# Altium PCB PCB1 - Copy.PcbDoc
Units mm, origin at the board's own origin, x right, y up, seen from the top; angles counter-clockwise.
Board outline 16 x 12 mm, 2 copper layers (Top Layer, Bottom Layer); 5 components, 7 nets, 19 pads, 7 vias.
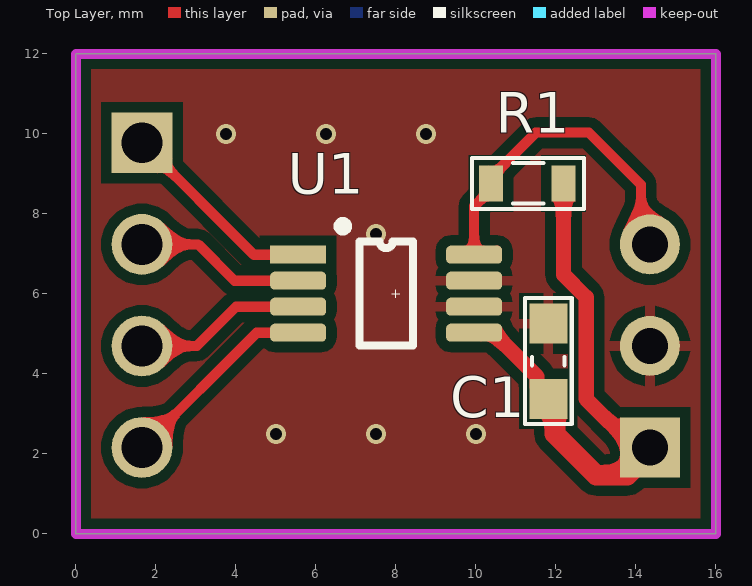
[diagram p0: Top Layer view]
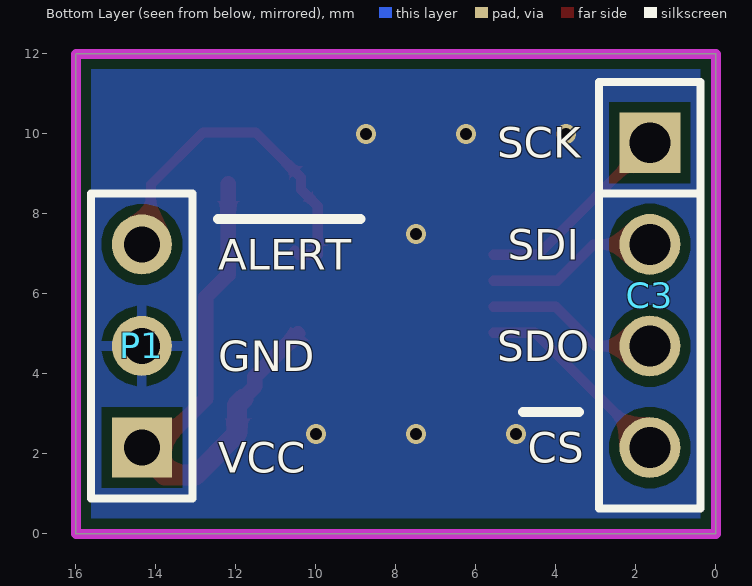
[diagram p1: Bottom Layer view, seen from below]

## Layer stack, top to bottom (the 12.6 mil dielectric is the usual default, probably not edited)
Top Solder: solder mask 0.0102, Solder Resist, Dk 3.5
Top Layer: signal copper 0.0356
Dielectric 1: dielectric 0.32, FR-4, Dk 4.8
Bottom Layer: signal copper 0.0356
Bottom Solder: solder mask 0.0102, Solder Resist, Dk 3.5

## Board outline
0,0 0,12 16,12 16,0

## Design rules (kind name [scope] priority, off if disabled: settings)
Clearance [All] p1: gap=0.254 ignorepadtopadclearanceinfootprint=TRUE
PolygonConnect [All] p1: connectstyle=Relief reliefconductorwidth=0.254 reliefentries=4 polygonreliefangle="90 Angle" airgapwidth=0.254
RoutingVias [All] p1: holewidth=0.711 width=1.27 viastyle="Through Hole" minholewidth=0.2 minwidth=0.3 maxholewidth=0.711 maxwidth=1.27
SolderMaskExpansion [All] p1: expansion=0.102 istentingtop=FALSE
Width [All] p1: maxlimit=1.27 minlimit=0.254 preferedwidth=0.254 minimp=50.000000 maximp=50.000000 favimp=50.000000
30 further rules are at their usual default settings.

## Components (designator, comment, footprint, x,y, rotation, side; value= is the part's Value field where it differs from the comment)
C1 "100nF" CAP_0603 11.811,4.318 r270 top value=33p
C3 "JP4" JP4-C1T 1.651,9.779 r270 bottom
P1 "Header 3" HDR1X3 14.351,2.159 r90 bottom
R1 "10k" RES-SMD-0603 11.303,8.763 r180 top
U1 "TMAG5170" SOP8 8,6 r0 top

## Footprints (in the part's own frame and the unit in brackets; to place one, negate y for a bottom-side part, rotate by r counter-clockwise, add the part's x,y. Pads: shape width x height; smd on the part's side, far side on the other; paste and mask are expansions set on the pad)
CAP_0603 [mm]
  rect 1x0.95 smd mask+0.076: 1(-0.94,0) 2(0.94,0)
  silkscreen extent -1.57,-0.58 1.57,0.58, body extent -0.77,-0.39 0.83,0.41, height 0.9
HDR1X3 [mm] "Connector; Header; 3 Position"
  rect 1.5x1.5 hole 0.9: 1(0,0)
  round 1.5 hole 0.9: 2(2.54,0) 3(5.08,0)
  silkscreen extent -1.27,-1.27 6.35,1.27, body extent -1.27,-1.27 6.35,1.27, height 7
JP4-C1T [mm] "4 row, straight, gold plating"
  rect 1.52x1.52 hole 1.02: 1(0,0)
  round 1.52 hole 1.02: 2(2.54,0) 3(5.08,0) 4(7.62,0)
  silkscreen extent -1.52,-1.27 9.14,1.27, body extent -1.52,-1.25 9.14,1.25, height 8.51
RES-SMD-0603 [mm]
  rect 0.6x0.9 smd: 1(-0.889,0) 2(0.927,0)
  silkscreen extent -1.4,-0.64 1.4,0.64, body extent -0.8,-0.4 0.8,0.4, height 0.43
SOP8 [mm]
  rect 1.4x0.45 smd: 1(-2.444,0.98)
  rrect50% 1.4x0.45 smd: 2(-2.444,0.33) 3(-2.444,-0.32) 4(-2.444,-0.97) 5(1.956,-0.97) 6(1.956,-0.32) 7(1.956,0.33) 8(1.956,0.98)
  silkscreen extent -1.43,-1.29 0.42,1.8

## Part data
C1: library part CapSMD, "Capacitor"
C3: "WR-PHD 2.54 mm Angled Socket Header", Manufacturer="W¨¹rth Elektronik eiSos GmbH", partNo=613004143121
P1: "Header, 3-Pin"
R1: library part "Resistor - SMD", "Resistor SMD", Manufacturer="Generic Components"

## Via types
v1: diameter 0.5, hole 0.3, Top Layer to Bottom Layer, 7 vias

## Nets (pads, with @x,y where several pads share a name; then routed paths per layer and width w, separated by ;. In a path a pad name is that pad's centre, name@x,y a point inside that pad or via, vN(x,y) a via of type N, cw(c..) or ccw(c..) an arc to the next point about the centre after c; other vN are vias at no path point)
3V3: C1.2 P1.1 R1.1 U1.5 | length 13.7
  Top Layer w0.381: U1.5@10.45,5.011 11.526,3.934 11.526,3.688 C1.2@11.811,3.403 ; R1.1 12.192,6.48 12.756,5.917 12.756,3.377 13.953,2.18 P1.1@14.224,1.909
  Top Layer w0.508: C1.2 11.974,3.215 11.974,2.504 13.01,1.468 13.784,1.468 P1.1@14.224,1.909
ALERT: P1.3 R1.2 U1.8 | length 9.3
  Top Layer w0.254: U1.8@10.529,7.078 10.431,6.98 U1.8 9.956,8.192 10.376,8.613 10.376,8.913 11.496,10.033 12.827,10.033 14.124,8.736 14.124,7.089 P1.3@14.224,6.989
CS: C3.4 U1.4 | length 5.1
  Top Layer w0.254: C3.4 4.522,5.03 U1.4
GND: C1.1 P1.2 U1.6 U1.7
  other v1: 5,2.5 7.5,2.5 10,2.5 7.5,7.5 3.75,10 6.25,10 8.75,10
MISO: C3.3 U1.3 | length 4.3
  Top Layer w0.254: C3.3 3.02,4.699 4.001,5.68 U1.3
MOSI: C3.2 U1.2 | length 4.3
  Top Layer w0.254: C3.2 3.056,7.239 3.965,6.33 U1.2
SCK: C3.1 U1.1 | length 5.1
  Top Layer w0.254: C3.1 4.45,6.98 U1.1

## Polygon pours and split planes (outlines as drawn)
GND on Top Layer "GND_L01_P000" (solid, pour order 0): 0.893,12.065 16.001,12.065 16.001,0 0.001,0 0.001,12.065 3.049,12.065
GND on Bottom Layer "GND_L02_P001" (solid, remove dead copper, pour order 1): 0,0 0,12.827 16.129,12.827 16.764,12.192 16.764,0

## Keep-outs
Keep-Out Layer:
  the board outline again, w0.254

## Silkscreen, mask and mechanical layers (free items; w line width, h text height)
Bottom Overlay:
  lines w0.254: 3.429,3.048 4.826,3.048 ; 8.89,7.874 12.446,7.874
  text "SCK" at 5.461,9.398 h0.76
  text "SDI" at 5.207,6.858 h0.76
  text "ALERT" at 12.446,6.604 h0.76
  text "SDO" at 5.461,4.318 h0.76
  text "GND" at 12.446,4.064 h0.76
  text "CS" at 4.699,1.778 h0.76
  text "VCC" at 12.446,1.524 h0.76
